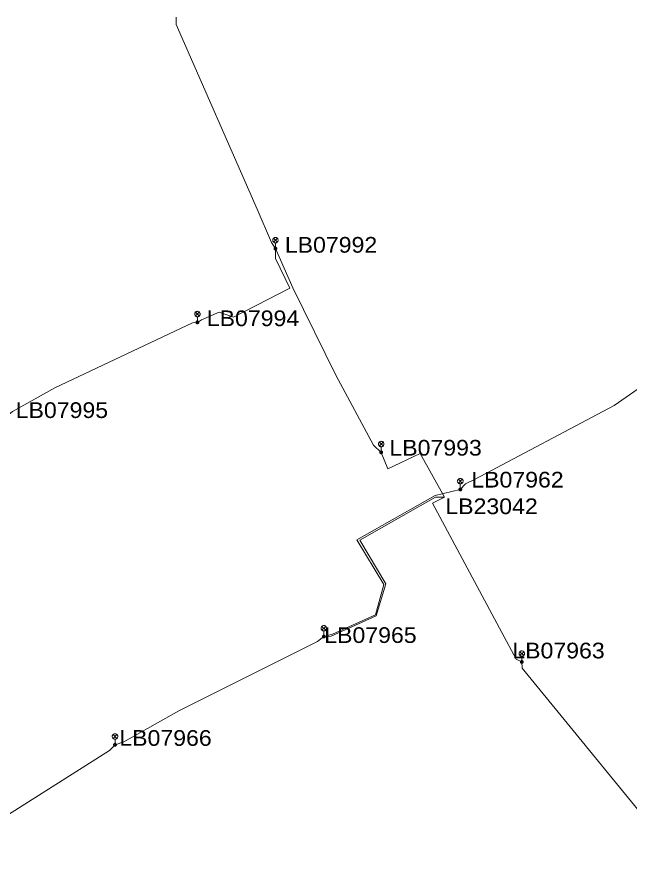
# Model space of a CAD drawing. Extents: x -688049 to -687261, y -973611 to -973038.
# Drawn here: x -687974.3 to -687889.6, y -973155.4 to -973037.9 of the extents above; entities that cross this region are included whole.
import ezdxf

# ---------------------------------------------------------------- set-up
doc = ezdxf.new("R2010")
doc.units = 0
doc.header["$LTSCALE"] = 0.87
doc.layers.add('1', color=7, linetype='Continuous', lineweight=13)

msp = doc.modelspace()

# ---------------------------------------------------------------- linework, layer by layer
at = {"layer": '1'}
for p, q in [((-687938.875, -973068.485), (-687938.345, -973069.015)), ((-687938.875, -973069.015), (-687938.345, -973068.485)), ((-687938.61, -973069.9), (-687938.61, -973069.125)), ((-687949.655, -973078.685), (-687949.125, -973079.215)), ((-687949.655, -973079.215), (-687949.125, -973078.685)), ((-687949.39, -973080.1), (-687949.39, -973079.325)), ((-687924.255, -973096.635), (-687923.725, -973097.165)), ((-687924.255, -973097.165), (-687923.725, -973096.635)), ((-687923.99, -973098.05), (-687923.99, -973097.275)), ((-687913.335, -973101.755), (-687912.805, -973102.285)), ((-687913.335, -973102.285), (-687912.805, -973101.755)), ((-687913.07, -973103.17), (-687913.07, -973102.395)), ((-687932.185, -973122.075), (-687931.655, -973122.605)), ((-687932.185, -973122.605), (-687931.655, -973122.075)), ((-687931.92, -973123.49), (-687931.92, -973122.715)), ((-687904.845, -973125.575), (-687904.315, -973126.105)), ((-687904.845, -973126.105), (-687904.315, -973125.575)), ((-687904.58, -973126.99), (-687904.58, -973126.215)), ((-687961.035, -973137.015), (-687960.505, -973137.545)), ((-687961.035, -973137.545), (-687960.505, -973137.015)), ((-687960.77, -973138.43), (-687960.77, -973137.655))]:
    msp.add_line(p, q, dxfattribs=at)
for points in [[(-687952.32, -973037.94), (-687952.32, -973038.962), (-687941.123, -973064.492), (-687939.141, -973069.052), (-687938.61, -973069.9)], [(-687938.61, -973069.9), (-687938.61, -973070.891), (-687938.604, -973071.274), (-687936.608, -973075.381), (-687944.415, -973079.364), (-687946.384, -973078.681), (-687948.831, -973079.747), (-687949.39, -973080.1)], [(-687938.61, -973069.9), (-687936.224, -973075.312), (-687930.288, -973087.4), (-687925.05, -973097.062), (-687923.99, -973098.05)], [(-687949.39, -973080.1), (-687950.072, -973080.165), (-687969.061, -973089.148), (-687974.93, -973092.414), (-687975.68, -973093.02)], [(-687884.12, -973086.94), (-687885.926, -973087.5), (-687891.829, -973091.595), (-687911.101, -973101.785), (-687912.338, -973102.386), (-687913.07, -973103.17)], [(-687915.25, -973104.23), (-687918.618, -973098.229), (-687923.105, -973100.33), (-687923.99, -973098.05)], [(-687913.07, -973103.17), (-687916.534, -973103.99), (-687927.369, -973110.127), (-687923.641, -973116.313), (-687924.788, -973120.501), (-687930.708, -973123.166), (-687931.92, -973123.49)], [(-687915.25, -973104.23), (-687916.481, -973104.23), (-687918.631, -973105.422), (-687926.938, -973110.169), (-687923.374, -973116.21), (-687924.703, -973120.633), (-687930.901, -973123.439), (-687931.92, -973123.49)], [(-687915.25, -973104.23), (-687916.911, -973105.057), (-687907.331, -973122.921), (-687905.366, -973126.618), (-687904.58, -973126.99)], [(-687960.77, -973138.43), (-687959.569, -973138.014), (-687951.95, -973133.754), (-687932.822, -973124.162), (-687931.92, -973123.49)], [(-687886, -973149.49), (-687886.922, -973149.337), (-687904.519, -973127.865), (-687904.58, -973126.99)], [(-687960.77, -973138.43), (-687961.54, -973139.222), (-687977.425, -973149.251), (-687986.227, -973155.219), (-687987.21, -973155.44)]]:
    msp.add_lwpolyline(points, dxfattribs=at)
for points in [[(-687938.235, -973068.75), (-687938.241, -973068.685), (-687938.258, -973068.622), (-687938.285, -973068.562), (-687938.323, -973068.509), (-687938.369, -973068.463), (-687938.422, -973068.425), (-687938.482, -973068.398), (-687938.545, -973068.381), (-687938.61, -973068.375), (-687938.675, -973068.381), (-687938.738, -973068.398), (-687938.798, -973068.425), (-687938.851, -973068.463), (-687938.897, -973068.509), (-687938.935, -973068.562), (-687938.962, -973068.622), (-687938.979, -973068.685), (-687938.985, -973068.75), (-687938.979, -973068.815), (-687938.962, -973068.878), (-687938.935, -973068.938), (-687938.897, -973068.991), (-687938.851, -973069.037), (-687938.798, -973069.075), (-687938.738, -973069.102), (-687938.675, -973069.119), (-687938.61, -973069.125), (-687938.545, -973069.119), (-687938.482, -973069.102), (-687938.422, -973069.075), (-687938.369, -973069.037), (-687938.323, -973068.991), (-687938.285, -973068.938), (-687938.258, -973068.878), (-687938.241, -973068.815)], [(-687938.42, -973069.9), (-687938.423, -973069.867), (-687938.431, -973069.835), (-687938.445, -973069.805), (-687938.464, -973069.778), (-687938.488, -973069.754), (-687938.515, -973069.735), (-687938.545, -973069.721), (-687938.577, -973069.713), (-687938.61, -973069.71), (-687938.643, -973069.713), (-687938.675, -973069.721), (-687938.705, -973069.735), (-687938.732, -973069.754), (-687938.756, -973069.778), (-687938.775, -973069.805), (-687938.789, -973069.835), (-687938.797, -973069.867), (-687938.8, -973069.9), (-687938.797, -973069.933), (-687938.789, -973069.965), (-687938.775, -973069.995), (-687938.756, -973070.022), (-687938.732, -973070.046), (-687938.705, -973070.065), (-687938.675, -973070.079), (-687938.643, -973070.087), (-687938.61, -973070.09), (-687938.577, -973070.087), (-687938.545, -973070.079), (-687938.515, -973070.065), (-687938.488, -973070.046), (-687938.464, -973070.022), (-687938.445, -973069.995), (-687938.431, -973069.965), (-687938.423, -973069.933)], [(-687938.56, -973069.9), (-687938.561, -973069.891), (-687938.563, -973069.883), (-687938.567, -973069.875), (-687938.572, -973069.868), (-687938.578, -973069.862), (-687938.585, -973069.857), (-687938.593, -973069.853), (-687938.601, -973069.851), (-687938.61, -973069.85), (-687938.619, -973069.851), (-687938.627, -973069.853), (-687938.635, -973069.857), (-687938.642, -973069.862), (-687938.648, -973069.868), (-687938.653, -973069.875), (-687938.657, -973069.883), (-687938.659, -973069.891), (-687938.66, -973069.9), (-687938.659, -973069.909), (-687938.657, -973069.917), (-687938.653, -973069.925), (-687938.648, -973069.932), (-687938.642, -973069.938), (-687938.635, -973069.943), (-687938.627, -973069.947), (-687938.619, -973069.949), (-687938.61, -973069.95), (-687938.601, -973069.949), (-687938.593, -973069.947), (-687938.585, -973069.943), (-687938.578, -973069.938), (-687938.572, -973069.932), (-687938.567, -973069.925), (-687938.563, -973069.917), (-687938.561, -973069.909)], [(-687949.015, -973078.95), (-687949.021, -973078.885), (-687949.038, -973078.822), (-687949.065, -973078.763), (-687949.103, -973078.709), (-687949.149, -973078.663), (-687949.202, -973078.625), (-687949.262, -973078.598), (-687949.325, -973078.581), (-687949.39, -973078.575), (-687949.455, -973078.581), (-687949.518, -973078.598), (-687949.578, -973078.625), (-687949.631, -973078.663), (-687949.677, -973078.709), (-687949.715, -973078.763), (-687949.742, -973078.822), (-687949.759, -973078.885), (-687949.765, -973078.95), (-687949.759, -973079.015), (-687949.742, -973079.078), (-687949.715, -973079.138), (-687949.677, -973079.191), (-687949.631, -973079.237), (-687949.578, -973079.275), (-687949.518, -973079.302), (-687949.455, -973079.319), (-687949.39, -973079.325), (-687949.325, -973079.319), (-687949.262, -973079.302), (-687949.202, -973079.275), (-687949.149, -973079.237), (-687949.103, -973079.191), (-687949.065, -973079.138), (-687949.038, -973079.078), (-687949.021, -973079.015)], [(-687949.2, -973080.1), (-687949.203, -973080.067), (-687949.211, -973080.035), (-687949.225, -973080.005), (-687949.244, -973079.978), (-687949.268, -973079.954), (-687949.295, -973079.935), (-687949.325, -973079.921), (-687949.357, -973079.913), (-687949.39, -973079.91), (-687949.423, -973079.913), (-687949.455, -973079.921), (-687949.485, -973079.935), (-687949.512, -973079.954), (-687949.536, -973079.978), (-687949.555, -973080.005), (-687949.569, -973080.035), (-687949.577, -973080.067), (-687949.58, -973080.1), (-687949.577, -973080.133), (-687949.569, -973080.165), (-687949.555, -973080.195), (-687949.536, -973080.222), (-687949.512, -973080.246), (-687949.485, -973080.265), (-687949.455, -973080.279), (-687949.423, -973080.287), (-687949.39, -973080.29), (-687949.357, -973080.287), (-687949.325, -973080.279), (-687949.295, -973080.265), (-687949.268, -973080.246), (-687949.244, -973080.222), (-687949.225, -973080.195), (-687949.211, -973080.165), (-687949.203, -973080.133)], [(-687949.34, -973080.1), (-687949.341, -973080.091), (-687949.343, -973080.083), (-687949.347, -973080.075), (-687949.352, -973080.068), (-687949.358, -973080.062), (-687949.365, -973080.057), (-687949.373, -973080.053), (-687949.381, -973080.051), (-687949.39, -973080.05), (-687949.399, -973080.051), (-687949.407, -973080.053), (-687949.415, -973080.057), (-687949.422, -973080.062), (-687949.428, -973080.068), (-687949.433, -973080.075), (-687949.437, -973080.083), (-687949.439, -973080.091), (-687949.44, -973080.1), (-687949.439, -973080.109), (-687949.437, -973080.117), (-687949.433, -973080.125), (-687949.428, -973080.132), (-687949.422, -973080.138), (-687949.415, -973080.143), (-687949.407, -973080.147), (-687949.399, -973080.149), (-687949.39, -973080.15), (-687949.381, -973080.149), (-687949.373, -973080.147), (-687949.365, -973080.143), (-687949.358, -973080.138), (-687949.352, -973080.132), (-687949.347, -973080.125), (-687949.343, -973080.117), (-687949.341, -973080.109)], [(-687923.615, -973096.9), (-687923.621, -973096.835), (-687923.638, -973096.772), (-687923.665, -973096.712), (-687923.703, -973096.659), (-687923.749, -973096.613), (-687923.802, -973096.575), (-687923.862, -973096.548), (-687923.925, -973096.531), (-687923.99, -973096.525), (-687924.055, -973096.531), (-687924.118, -973096.548), (-687924.178, -973096.575), (-687924.231, -973096.613), (-687924.277, -973096.659), (-687924.315, -973096.712), (-687924.342, -973096.772), (-687924.359, -973096.835), (-687924.365, -973096.9), (-687924.359, -973096.965), (-687924.342, -973097.028), (-687924.315, -973097.088), (-687924.277, -973097.141), (-687924.231, -973097.187), (-687924.178, -973097.225), (-687924.118, -973097.252), (-687924.055, -973097.269), (-687923.99, -973097.275), (-687923.925, -973097.269), (-687923.862, -973097.252), (-687923.802, -973097.225), (-687923.749, -973097.187), (-687923.703, -973097.141), (-687923.665, -973097.088), (-687923.638, -973097.028), (-687923.621, -973096.965)], [(-687923.8, -973098.05), (-687923.803, -973098.017), (-687923.811, -973097.985), (-687923.825, -973097.955), (-687923.844, -973097.928), (-687923.868, -973097.904), (-687923.895, -973097.885), (-687923.925, -973097.871), (-687923.957, -973097.863), (-687923.99, -973097.86), (-687924.023, -973097.863), (-687924.055, -973097.871), (-687924.085, -973097.885), (-687924.112, -973097.904), (-687924.136, -973097.928), (-687924.155, -973097.955), (-687924.169, -973097.985), (-687924.177, -973098.017), (-687924.18, -973098.05), (-687924.177, -973098.083), (-687924.169, -973098.115), (-687924.155, -973098.145), (-687924.136, -973098.172), (-687924.112, -973098.196), (-687924.085, -973098.215), (-687924.055, -973098.229), (-687924.023, -973098.237), (-687923.99, -973098.24), (-687923.957, -973098.237), (-687923.925, -973098.229), (-687923.895, -973098.215), (-687923.868, -973098.196), (-687923.844, -973098.172), (-687923.825, -973098.145), (-687923.811, -973098.115), (-687923.803, -973098.083)], [(-687923.94, -973098.05), (-687923.941, -973098.041), (-687923.943, -973098.033), (-687923.947, -973098.025), (-687923.952, -973098.018), (-687923.958, -973098.012), (-687923.965, -973098.007), (-687923.973, -973098.003), (-687923.981, -973098.001), (-687923.99, -973098), (-687923.999, -973098.001), (-687924.007, -973098.003), (-687924.015, -973098.007), (-687924.022, -973098.012), (-687924.028, -973098.018), (-687924.033, -973098.025), (-687924.037, -973098.033), (-687924.039, -973098.041), (-687924.04, -973098.05), (-687924.039, -973098.059), (-687924.037, -973098.067), (-687924.033, -973098.075), (-687924.028, -973098.082), (-687924.022, -973098.088), (-687924.015, -973098.093), (-687924.007, -973098.097), (-687923.999, -973098.099), (-687923.99, -973098.1), (-687923.981, -973098.099), (-687923.973, -973098.097), (-687923.965, -973098.093), (-687923.958, -973098.088), (-687923.952, -973098.082), (-687923.947, -973098.075), (-687923.943, -973098.067), (-687923.941, -973098.059)], [(-687912.695, -973102.02), (-687912.701, -973101.955), (-687912.718, -973101.892), (-687912.745, -973101.832), (-687912.783, -973101.779), (-687912.829, -973101.733), (-687912.883, -973101.695), (-687912.942, -973101.668), (-687913.005, -973101.651), (-687913.07, -973101.645), (-687913.135, -973101.651), (-687913.198, -973101.668), (-687913.258, -973101.695), (-687913.311, -973101.733), (-687913.357, -973101.779), (-687913.395, -973101.832), (-687913.422, -973101.892), (-687913.439, -973101.955), (-687913.445, -973102.02), (-687913.439, -973102.085), (-687913.422, -973102.148), (-687913.395, -973102.208), (-687913.357, -973102.261), (-687913.311, -973102.307), (-687913.258, -973102.345), (-687913.198, -973102.372), (-687913.135, -973102.389), (-687913.07, -973102.395), (-687913.005, -973102.389), (-687912.942, -973102.372), (-687912.883, -973102.345), (-687912.829, -973102.307), (-687912.783, -973102.261), (-687912.745, -973102.208), (-687912.718, -973102.148), (-687912.701, -973102.085)], [(-687912.88, -973103.17), (-687912.883, -973103.137), (-687912.891, -973103.105), (-687912.905, -973103.075), (-687912.924, -973103.048), (-687912.948, -973103.024), (-687912.975, -973103.005), (-687913.005, -973102.991), (-687913.037, -973102.983), (-687913.07, -973102.98), (-687913.103, -973102.983), (-687913.135, -973102.991), (-687913.165, -973103.005), (-687913.192, -973103.024), (-687913.216, -973103.048), (-687913.235, -973103.075), (-687913.249, -973103.105), (-687913.257, -973103.137), (-687913.26, -973103.17), (-687913.257, -973103.203), (-687913.249, -973103.235), (-687913.235, -973103.265), (-687913.216, -973103.292), (-687913.192, -973103.316), (-687913.165, -973103.335), (-687913.135, -973103.349), (-687913.103, -973103.357), (-687913.07, -973103.36), (-687913.037, -973103.357), (-687913.005, -973103.349), (-687912.975, -973103.335), (-687912.948, -973103.316), (-687912.924, -973103.292), (-687912.905, -973103.265), (-687912.891, -973103.235), (-687912.883, -973103.203)], [(-687913.02, -973103.17), (-687913.021, -973103.161), (-687913.023, -973103.153), (-687913.027, -973103.145), (-687913.032, -973103.138), (-687913.038, -973103.132), (-687913.045, -973103.127), (-687913.053, -973103.123), (-687913.061, -973103.121), (-687913.07, -973103.12), (-687913.079, -973103.121), (-687913.087, -973103.123), (-687913.095, -973103.127), (-687913.102, -973103.132), (-687913.108, -973103.138), (-687913.113, -973103.145), (-687913.117, -973103.153), (-687913.119, -973103.161), (-687913.12, -973103.17), (-687913.119, -973103.179), (-687913.117, -973103.187), (-687913.113, -973103.195), (-687913.108, -973103.202), (-687913.102, -973103.208), (-687913.095, -973103.213), (-687913.087, -973103.217), (-687913.079, -973103.219), (-687913.07, -973103.22), (-687913.061, -973103.219), (-687913.053, -973103.217), (-687913.045, -973103.213), (-687913.038, -973103.208), (-687913.032, -973103.202), (-687913.027, -973103.195), (-687913.023, -973103.187), (-687913.021, -973103.179)], [(-687931.545, -973122.34), (-687931.551, -973122.275), (-687931.568, -973122.212), (-687931.595, -973122.153), (-687931.633, -973122.099), (-687931.679, -973122.053), (-687931.732, -973122.015), (-687931.792, -973121.988), (-687931.855, -973121.971), (-687931.92, -973121.965), (-687931.985, -973121.971), (-687932.048, -973121.988), (-687932.108, -973122.015), (-687932.161, -973122.053), (-687932.207, -973122.099), (-687932.245, -973122.153), (-687932.272, -973122.212), (-687932.289, -973122.275), (-687932.295, -973122.34), (-687932.289, -973122.405), (-687932.272, -973122.468), (-687932.245, -973122.528), (-687932.207, -973122.581), (-687932.161, -973122.627), (-687932.108, -973122.665), (-687932.048, -973122.692), (-687931.985, -973122.709), (-687931.92, -973122.715), (-687931.855, -973122.709), (-687931.792, -973122.692), (-687931.732, -973122.665), (-687931.679, -973122.627), (-687931.633, -973122.581), (-687931.595, -973122.528), (-687931.568, -973122.468), (-687931.551, -973122.405)], [(-687931.73, -973123.49), (-687931.733, -973123.457), (-687931.741, -973123.425), (-687931.755, -973123.395), (-687931.774, -973123.368), (-687931.798, -973123.344), (-687931.825, -973123.325), (-687931.855, -973123.311), (-687931.887, -973123.303), (-687931.92, -973123.3), (-687931.953, -973123.303), (-687931.985, -973123.311), (-687932.015, -973123.325), (-687932.042, -973123.344), (-687932.066, -973123.368), (-687932.085, -973123.395), (-687932.099, -973123.425), (-687932.107, -973123.457), (-687932.11, -973123.49), (-687932.107, -973123.523), (-687932.099, -973123.555), (-687932.085, -973123.585), (-687932.066, -973123.612), (-687932.042, -973123.636), (-687932.015, -973123.655), (-687931.985, -973123.669), (-687931.953, -973123.677), (-687931.92, -973123.68), (-687931.887, -973123.677), (-687931.855, -973123.669), (-687931.825, -973123.655), (-687931.798, -973123.636), (-687931.774, -973123.612), (-687931.755, -973123.585), (-687931.741, -973123.555), (-687931.733, -973123.523)], [(-687931.87, -973123.49), (-687931.871, -973123.481), (-687931.873, -973123.473), (-687931.877, -973123.465), (-687931.882, -973123.458), (-687931.888, -973123.452), (-687931.895, -973123.447), (-687931.903, -973123.443), (-687931.911, -973123.441), (-687931.92, -973123.44), (-687931.929, -973123.441), (-687931.937, -973123.443), (-687931.945, -973123.447), (-687931.952, -973123.452), (-687931.958, -973123.458), (-687931.963, -973123.465), (-687931.967, -973123.473), (-687931.969, -973123.481), (-687931.97, -973123.49), (-687931.969, -973123.499), (-687931.967, -973123.507), (-687931.963, -973123.515), (-687931.958, -973123.522), (-687931.952, -973123.528), (-687931.945, -973123.533), (-687931.937, -973123.537), (-687931.929, -973123.539), (-687931.92, -973123.54), (-687931.911, -973123.539), (-687931.903, -973123.537), (-687931.895, -973123.533), (-687931.888, -973123.528), (-687931.882, -973123.522), (-687931.877, -973123.515), (-687931.873, -973123.507), (-687931.871, -973123.499)], [(-687904.205, -973125.84), (-687904.211, -973125.775), (-687904.228, -973125.712), (-687904.255, -973125.653), (-687904.293, -973125.599), (-687904.339, -973125.553), (-687904.392, -973125.515), (-687904.452, -973125.488), (-687904.515, -973125.471), (-687904.58, -973125.465), (-687904.645, -973125.471), (-687904.708, -973125.488), (-687904.768, -973125.515), (-687904.821, -973125.553), (-687904.867, -973125.599), (-687904.905, -973125.653), (-687904.932, -973125.712), (-687904.949, -973125.775), (-687904.955, -973125.84), (-687904.949, -973125.905), (-687904.932, -973125.968), (-687904.905, -973126.028), (-687904.867, -973126.081), (-687904.821, -973126.127), (-687904.768, -973126.165), (-687904.708, -973126.192), (-687904.645, -973126.209), (-687904.58, -973126.215), (-687904.515, -973126.209), (-687904.452, -973126.192), (-687904.392, -973126.165), (-687904.339, -973126.127), (-687904.293, -973126.081), (-687904.255, -973126.028), (-687904.228, -973125.968), (-687904.211, -973125.905)], [(-687904.39, -973126.99), (-687904.393, -973126.957), (-687904.401, -973126.925), (-687904.415, -973126.895), (-687904.434, -973126.868), (-687904.458, -973126.844), (-687904.485, -973126.825), (-687904.515, -973126.811), (-687904.547, -973126.803), (-687904.58, -973126.8), (-687904.613, -973126.803), (-687904.645, -973126.811), (-687904.675, -973126.825), (-687904.702, -973126.844), (-687904.726, -973126.868), (-687904.745, -973126.895), (-687904.759, -973126.925), (-687904.767, -973126.957), (-687904.77, -973126.99), (-687904.767, -973127.023), (-687904.759, -973127.055), (-687904.745, -973127.085), (-687904.726, -973127.112), (-687904.702, -973127.136), (-687904.675, -973127.155), (-687904.645, -973127.169), (-687904.613, -973127.177), (-687904.58, -973127.18), (-687904.547, -973127.177), (-687904.515, -973127.169), (-687904.485, -973127.155), (-687904.458, -973127.136), (-687904.434, -973127.112), (-687904.415, -973127.085), (-687904.401, -973127.055), (-687904.393, -973127.023)], [(-687904.53, -973126.99), (-687904.531, -973126.981), (-687904.533, -973126.973), (-687904.537, -973126.965), (-687904.542, -973126.958), (-687904.548, -973126.952), (-687904.555, -973126.947), (-687904.563, -973126.943), (-687904.571, -973126.941), (-687904.58, -973126.94), (-687904.589, -973126.941), (-687904.597, -973126.943), (-687904.605, -973126.947), (-687904.612, -973126.952), (-687904.618, -973126.958), (-687904.623, -973126.965), (-687904.627, -973126.973), (-687904.629, -973126.981), (-687904.63, -973126.99), (-687904.629, -973126.999), (-687904.627, -973127.007), (-687904.623, -973127.015), (-687904.618, -973127.022), (-687904.612, -973127.028), (-687904.605, -973127.033), (-687904.597, -973127.037), (-687904.589, -973127.039), (-687904.58, -973127.04), (-687904.571, -973127.039), (-687904.563, -973127.037), (-687904.555, -973127.033), (-687904.548, -973127.028), (-687904.542, -973127.022), (-687904.537, -973127.015), (-687904.533, -973127.007), (-687904.531, -973126.999)], [(-687960.395, -973137.28), (-687960.401, -973137.215), (-687960.418, -973137.152), (-687960.445, -973137.092), (-687960.483, -973137.039), (-687960.529, -973136.993), (-687960.582, -973136.955), (-687960.642, -973136.928), (-687960.705, -973136.911), (-687960.77, -973136.905), (-687960.835, -973136.911), (-687960.898, -973136.928), (-687960.958, -973136.955), (-687961.011, -973136.993), (-687961.057, -973137.039), (-687961.095, -973137.092), (-687961.122, -973137.152), (-687961.139, -973137.215), (-687961.145, -973137.28), (-687961.139, -973137.345), (-687961.122, -973137.408), (-687961.095, -973137.468), (-687961.057, -973137.521), (-687961.011, -973137.567), (-687960.958, -973137.605), (-687960.898, -973137.632), (-687960.835, -973137.649), (-687960.77, -973137.655), (-687960.705, -973137.649), (-687960.642, -973137.632), (-687960.582, -973137.605), (-687960.529, -973137.567), (-687960.483, -973137.521), (-687960.445, -973137.468), (-687960.418, -973137.408), (-687960.401, -973137.345)], [(-687960.58, -973138.43), (-687960.583, -973138.397), (-687960.591, -973138.365), (-687960.605, -973138.335), (-687960.624, -973138.308), (-687960.648, -973138.284), (-687960.675, -973138.265), (-687960.705, -973138.251), (-687960.737, -973138.243), (-687960.77, -973138.24), (-687960.803, -973138.243), (-687960.835, -973138.251), (-687960.865, -973138.265), (-687960.892, -973138.284), (-687960.916, -973138.308), (-687960.935, -973138.335), (-687960.949, -973138.365), (-687960.957, -973138.397), (-687960.96, -973138.43), (-687960.957, -973138.463), (-687960.949, -973138.495), (-687960.935, -973138.525), (-687960.916, -973138.552), (-687960.892, -973138.576), (-687960.865, -973138.595), (-687960.835, -973138.609), (-687960.803, -973138.617), (-687960.77, -973138.62), (-687960.737, -973138.617), (-687960.705, -973138.609), (-687960.675, -973138.595), (-687960.648, -973138.576), (-687960.624, -973138.552), (-687960.605, -973138.525), (-687960.591, -973138.495), (-687960.583, -973138.463)], [(-687960.72, -973138.43), (-687960.721, -973138.421), (-687960.723, -973138.413), (-687960.727, -973138.405), (-687960.732, -973138.398), (-687960.738, -973138.392), (-687960.745, -973138.387), (-687960.753, -973138.383), (-687960.761, -973138.381), (-687960.77, -973138.38), (-687960.779, -973138.381), (-687960.787, -973138.383), (-687960.795, -973138.387), (-687960.802, -973138.392), (-687960.808, -973138.398), (-687960.813, -973138.405), (-687960.817, -973138.413), (-687960.819, -973138.421), (-687960.82, -973138.43), (-687960.819, -973138.439), (-687960.817, -973138.447), (-687960.813, -973138.455), (-687960.808, -973138.462), (-687960.802, -973138.468), (-687960.795, -973138.473), (-687960.787, -973138.477), (-687960.779, -973138.479), (-687960.77, -973138.48), (-687960.761, -973138.479), (-687960.753, -973138.477), (-687960.745, -973138.473), (-687960.738, -973138.468), (-687960.732, -973138.462), (-687960.727, -973138.455), (-687960.723, -973138.447), (-687960.721, -973138.439)]]:
    msp.add_lwpolyline(points, close=True, dxfattribs=at)

# ---------------------------------------------------------------- texts
at = {"layer": '1', "width": 1.1}
for s, height, p in [('LB07992', 2.167, (-687937.311, -973070.479)), ('LB07994', 2.167, (-687948.092, -973080.623)), ('LB07995', 2.167, (-687974.487, -973093.307)), ('LB07993', 2.167, (-687922.868, -973098.501)), ('LB07962', 2.167, (-687911.558, -973102.908)), ('LB23042', 2.168, (-687915.145, -973106.579)), ('LB07965', 2.167, (-687931.868, -973124.368)), ('LB07963', 2.167, (-687905.891, -973126.5)), ('LB07966', 2.167, (-687960.174, -973138.572))]:
    msp.add_text(s, height=height, dxfattribs=at).set_placement(p)

doc.saveas('drawing.dxf')
